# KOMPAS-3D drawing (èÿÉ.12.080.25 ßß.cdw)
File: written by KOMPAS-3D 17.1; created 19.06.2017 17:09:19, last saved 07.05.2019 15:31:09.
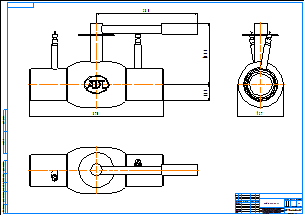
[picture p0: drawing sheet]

Sheet 1: A1, landscape

Title block, sheet 1: name: КШР.12.080.25 сс; material: Внимание! Данный продукт является объектом авторского права ООО «Торговый Дом АДЛ». / Запрещается изменение, копирование, распространение / (в том числе путем копирования на другие сайты и ресурсы в Интернете) / или любое иное использование информации и объектов без предварительного / согласия правообладателя (ООО «Торговый Дом АДЛ»).; scale: 1:1; sheets: 1; organisation: ООО "Торговый дом АДЛ"; sheet format: A1; stored path: C:\Users\tra\Desktop\2д чертежи\Шаровые краны БИВАЛ\КШР_Бивал_серия_12\KOMPAS 2D\КШР.12.080.25 сс.cdw

Views: Спереди 1, Проекционный вид 2, Проекционный вид 3
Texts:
  Klimkovich
  ADL
Dimensions and other numbers on the sheet: 370; 280; 168,8; 44,5; 127; 1:1; 1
